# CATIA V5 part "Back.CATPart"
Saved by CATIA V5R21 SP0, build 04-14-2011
Part number: Back
Bounding box of the stored display mesh (mm): x -92.8 to 92.8, y 0 to 2.8, z -5 to 133.511
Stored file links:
  C:\Users\Pouria\Desktop\Box\Assembled\Back.CATPart
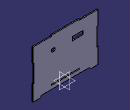
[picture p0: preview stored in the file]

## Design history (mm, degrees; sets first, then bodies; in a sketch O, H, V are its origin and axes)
Body1 (main body)
  Sketch1 on zx-plane, origin (0, 0, 0), H (-1, 0, 0), V (0, 0, 1)
    point P1 (-92.8, 0)
    line L1 (-67.8, 0) -> (67.8, 0)
    line L2 (92.8, 0) -> (92.8, 40)
    line L3 (92.8, 130.711) -> (40, 130.711)
    line L4 (-92.8, 130.711) -> (-92.8, 90)
    point P2 (92.8, 0)
    point P3 (92.8, 130.711)
    point P4 (-92.8, 130.711)
    point P5 (0, 11.4)
    line L5 (40, 12.8) -> (40, 10)
    line L6 (40, 10) -> (-40, 10)
    line L7 (-40, 10) -> (-40, 12.8)
    line L8 (-40, 12.8) -> (40, 12.8)
    line L9 (92.8, 0) -> (92.8, -5)
    line L10 (92.8, -5) -> (72.8, -5)
    line L11 (72.8, -5) -> (67.8, 0)
    line L12 (-92.8, 0) -> (-92.8, -5)
    line L13 (-92.8, -5) -> (-72.8, -5)
    line L14 (-72.8, -5) -> (-67.8, 0)
    point P16 (92.8, 90)
    line L15 (92.8, 90) -> (90, 90)
    line L16 (90, 90) -> (90, 40)
    line L17 (90, 40) -> (92.8, 40)
    line L18 (-92.8, 90) -> (-90, 90)
    line L19 (-90, 90) -> (-90, 40)
    line L20 (-90, 40) -> (-92.8, 40)
    point P23 (-92.8, 40)
    point P24 (-40, 130.711)
    line L21 (-40, 130.711) -> (-40, 133.511)
    line L22 (-40, 133.511) -> (40, 133.511)
    line L23 (40, 133.511) -> (40, 130.711)
    line L24 (92.8, 90) -> (92.8, 130.711)
    line L25 (-40, 130.711) -> (-92.8, 130.711)
    line L26 (-92.8, 40) -> (-92.8, 0)
    distance L6 L1 = 10
    length L5 = 2.8
    length L8 = 80
    length L9 = 5
    length L10 = 20
    length L12 = 5
    length L13 = 20
    angle L14 L1 = 45
    angle L11 L1 = 45
    length L21 = 2.8
    length L22 = 80
    length L15 = 2.8
    length L18 = 2.8
    length L16 = 50
    length L19 = 50
    distance L20 H = 40
    distance L17 H = 40
    distance P2 P3 = 130.711
    distance P3 P4 = 185.6
    coincidence: P1 H, P5 V, P2 H, P16 L2, P23 L4, P24 L3, L2 L24, L3 L25, L4 L26, L1 H
    horizontal: L1 H, L3 H, L6 H, L8 H, L10 H, L13 H, L15 H, L17 H, L18 H, L20 H, L22 H, L25 H
    vertical: L2 V, L4 V, L5 V, L7 V, L9 V, L12 V, L16 V, L19 V, L21 V, L23 V, L24 V, L26 V
    symmetry: L2 L4 V, L23 L21 V
    equidistance: L5 L7 P5, L6 L8 P5
  Pad1: profile Sketch1, direction (0, 1, 0), length 2.8
  Sketch2 on end face of Pad1, origin (0, 2.8, 0), H (-1, 0, 0), V (0, 0, 1)
    point P1 (35, 95.25)
    line L1 (50.5, 100.5) -> (50.5, 90)
    line L2 (50.5, 90) -> (19.5, 90)
    line L3 (19.5, 90) -> (19.5, 100.5)
    line L4 (19.5, 100.5) -> (50.5, 100.5)
    arc A1 centre (-35, 95.25) radius 5.5 from (-37.7726, 100) to (-37.7726, 90.5) ccw
    point P6 (-35, 95.25)
    line L5 (-37.7726, 100) -> (-32.2274, 100)
    line L6 (-37.7726, 90.5) -> (-32.2274, 90.5)
    point P10 (-32.2274, 90.5)
    reference projected line E1 (-90, 90) -> (-90, 40) from edge [face of Pad1 from Sketch1.L19 | end face of Pad1]
    reference projected line E2 (90, 40) -> (90, 90) from edge [face of Pad1 from Sketch1.L16 | end face of Pad1]
    arc A2 centre (-35, 95.25) radius 5.5 from (-32.2274, 90.5) to (-32.2274, 100) ccw
    length L1 = 10.5
    length L4 = 31
    radius A1 = 5.5
    distance L6 L5 = 9.5
    distance P6 P1 V = 0
    distance P6 L5 = 4.75
    distance H L2 = 90
    distance P6 E1 = 55
    distance P1 E2 = 55
    vertical: L1 V, L3 V
    horizontal: L2 H, L4 H, L5 H, L6 H
    equidistance: L1 L3 P1, L2 L4 P1
    coincidence: P10 A1, A1 A2
    parallelism: L5 L6
  Pocket1: profile Sketch2, direction (0, -1, 0), through (limit type 3)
